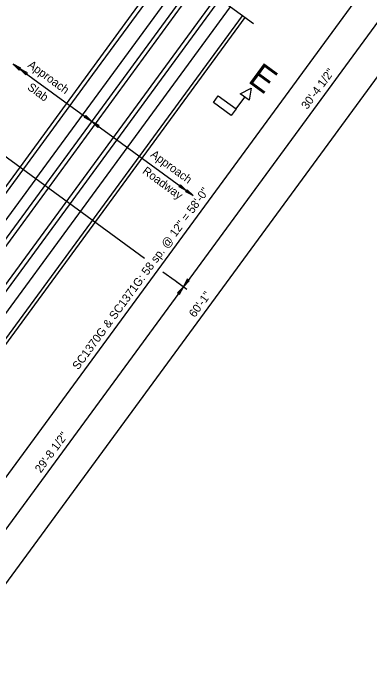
# Model space of a CAD drawing. Extents: x 1970654 to 1970899, y 796145 to 796378.
# Drawn here: x 1970776.66 to 1970798.14, y 796224.7 to 796264.53 of the extents above; entities that cross this region are included whole.
import ezdxf

# ---------------------------------------------------------------- set-up
doc = ezdxf.new("R2010")
doc.units = 0
for name, color, linetype in [('BR_AUTO DIMENSION', 7, 'Continuous'), ('BR_CENTER LINES', 7, 'Continuous'), ('BR_CONCRETE', 7, 'Continuous'), ('BR_REBAR', 7, 'Continuous'), ('BR_TABLE LINES', 7, 'Continuous'), ('BR_TEXT', 7, 'Continuous')]:
    doc.layers.add(name, color=color, linetype=linetype)

# ---------------------------------------------------------------- blocks, each defined once
blk = doc.blocks.new('B')
at = {"layer": 'BR_AUTO DIMENSION'}
blk.add_lwpolyline([(-0.2, 0.03), (0, 0), (-0.2, -0.03)], close=True, dxfattribs=at)
blk = doc.blocks.new('ARROW')
at = {"layer": 'BR_AUTO DIMENSION', "xscale": 0.625, "yscale": 0.625}
blk.add_blockref('B', (0, 0), dxfattribs=at)
blk = doc.blocks.new('DAH')
at = {"layer": 'BR_AUTO DIMENSION'}
for p in [(-0.1248, 0), (0, 0)]:
    blk.add_blockref('ARROW', p, dxfattribs=at)

msp = doc.modelspace()

# ---------------------------------------------------------------- linework, layer by layer
at = {"layer": 'BR_AUTO DIMENSION'}
for p, q in [((1970802.667, 796272.689), (1970768.229, 796225.652)), ((1970803.156, 796270.225), (1970770.665, 796225.847)), ((1970772.237, 796224.696), (1970804.728, 796269.074)), ((1970791.136, 796263.888), (1970788.752, 796265.634)), ((1970776.666, 796261.458), (1970781.393, 796257.997)), ((1970781.393, 796257.997), (1970787.497, 796253.528)), ((1970786.408, 796248.404), (1970787.112, 796247.888)), ((1970786.511, 796248.329), (1970787.112, 796247.888))]:
    msp.add_line(p, q, dxfattribs=at)
for points in [[(1970777.114, 796261.223), (1970776.666, 796261.458), (1970777.025, 796261.102)], [(1970777.512, 796260.932), (1970777.065, 796261.167), (1970777.424, 796260.811)], [(1970781.034, 796258.353), (1970781.393, 796257.997), (1970780.946, 796258.232)], [(1970781.841, 796257.762), (1970781.393, 796257.997), (1970781.753, 796257.641)], [(1970787.145, 796248.484), (1970786.91, 796248.036), (1970787.266, 796248.395)], [(1970786.676, 796247.588), (1970786.91, 796248.036), (1970786.555, 796247.677)]]:
    msp.add_lwpolyline(points, close=True, dxfattribs=at)
at = {"layer": 'BR_CENTER LINES'}
for p, q in [((1970767.894, 796261.959), (1970784.565, 796249.753)), ((1970785.677, 796248.939), (1970786.408, 796248.404))]:
    msp.add_line(p, q, dxfattribs=at)
at = {"layer": 'BR_CONCRETE'}
for p, q in [((1970771.606, 796247.804), (1970786.088, 796267.584)), ((1970773.119, 796246.696), (1970787.601, 796266.476)), ((1970774.632, 796245.588), (1970789.114, 796265.368)), ((1970776.145, 796244.481), (1970790.627, 796264.261))]:
    msp.add_line(p, q, dxfattribs=at)
at = {"layer": 'BR_REBAR'}
for p, q in [((1970781.449, 796260.823), (1970786.29, 796267.436)), ((1970778.016, 796254.548), (1970787.046, 796266.882)), ((1970773.321, 796246.548), (1970787.803, 796266.328)), ((1970774.428, 796245.737), (1970788.91, 796265.517)), ((1970775.262, 796245.127), (1970789.744, 796264.907)), ((1970775.987, 796244.596), (1970790.469, 796264.376)), ((1970771.808, 796247.656), (1970781.449, 796260.823)), ((1970778.016, 796254.548), (1970772.564, 796247.102))]:
    msp.add_line(p, q, dxfattribs=at)
at = {"layer": 'BR_TABLE LINES'}
msp.add_line((1970790.084, 796258.758), (1970790.609, 796259.475), dxfattribs=at)
for points in [[(1970790.34, 796259.672), (1970791.003, 796260.013), (1970790.878, 796259.278)], [(1970788.72, 796259.151), (1970789.008, 796259.546), (1970790.084, 796258.758), (1970789.795, 796258.363)]]:
    msp.add_lwpolyline(points, close=True, dxfattribs=at)

# ---------------------------------------------------------------- block references
at = {"layer": 'BR_TEXT', "xscale": 4.00000005, "yscale": 4.000000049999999, "rotation": -36.20941800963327}
msp.add_blockref('DAH', (1970787.497, 796253.528), dxfattribs=at)

# ---------------------------------------------------------------- texts
at = {"layer": 'BR_AUTO DIMENSION'}
for s, p in [('30\'-4 1/2"', (1970794.369, 796258.69)), ('SC1370G & SC1371G: 58 sp. @ 12" = 58\'-0"', (1970780.578, 796242.985)), ('60\'-1"', (1970787.598, 796246.143)), ('29\'-8 1/2"', (1970778.322, 796236.772))]:
    msp.add_text(s, height=0.5, rotation=53.7906, dxfattribs=at).set_placement(p)
at = {"layer": 'BR_TEXT'}
for s, height, p in [('Approach', 0.4999, (1970777.492, 796261.318)), ('E', 1.5, (1970790.743, 796260.403)), (' Slab', 0.4999, (1970777.322, 796260.078)), ('Approach', 0.4999, (1970784.891, 796255.918)), ('Roadway', 0.4999, (1970784.399, 796254.915))]:
    msp.add_text(s, height=height, rotation=323.7906, dxfattribs=at).set_placement(p)

doc.saveas('drawing.dxf')
